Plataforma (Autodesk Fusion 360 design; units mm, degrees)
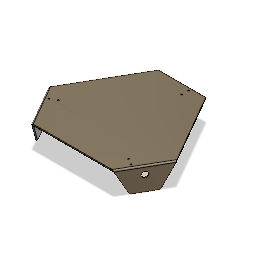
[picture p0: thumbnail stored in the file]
sketch "Sketch1" plane through (0, 0, 0) normal (0, 1, 0) x axis (1, 0, 0)
  dimension "d12" = 200.1666
  dimension "d13" = 200.1666
  dimension "d14" = 200.1666
  dimension "d17" = 360
  dimension "d50" = 3
  dimension "d51" = 3
  dimension "d52" = 20
  dimension "d53" = 20
  dimension "d54" = 6
  dimension "d55" = 15
extrude "Extrude1" new body sketch "Sketch1" along normal blind 3
sketch "Sketch1" plane through (115.1814, 0, 66.5) normal (0.866, 0, 0.5) x axis (0.5, 0, -0.866)
  dimension "d20" = 47
fillet "Fillet1" radius 3
circular_pattern "C-Pattern1" TotalAngle 360
extrude "Extrude1" new body sketch "Sketch1" against normal blind 3
sketch "Sketch2" plane through (115.1814, 0, 66.5) normal (0.866, 0, 0.5) x axis (0.5, 0, -0.866)
  dimension "d27" = 12
extrude "Extrude2" cut sketch "Sketch2" against normal blind 3
sketch "Sketch3" plane through (115.1814, 0, 66.5) normal (0.866, 0, 0.5) x axis (0.5, 0, -0.866)
sketch "Sketch1" plane through (0, 3, 0) normal (0, 1, 0) x axis (-1, 0, 0)
extrude "Extrude2" cut sketch "Sketch1" along normal blind 3
circular_pattern "C-Pattern2" TotalAngle 360
circular_pattern "C-Pattern1" TotalAngle 360
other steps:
create_component "CreateComponent1"
create_component "CreateComponent2"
